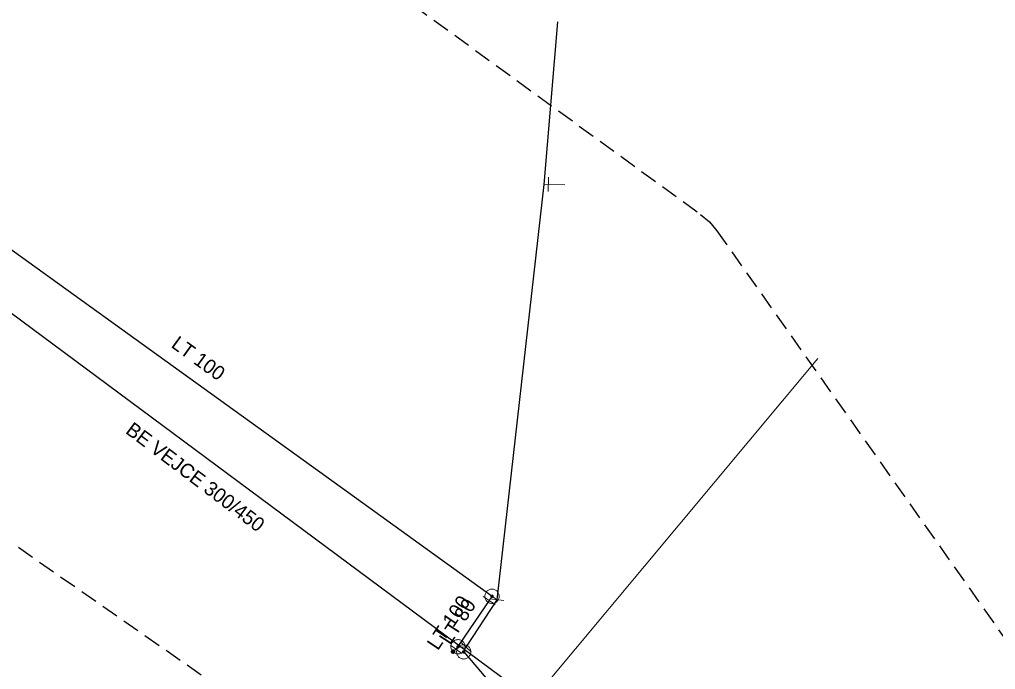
# Model space of a CAD drawing. Extents: x -749365 to -748625, y -965388 to -964881.
# Drawn here: x -748769.4 to -748701, y -965272.1 to -965226.5 of the extents above; entities that cross this region are included whole.
import ezdxf

# ---------------------------------------------------------------- set-up
doc = ezdxf.new("R2010")
doc.units = 0
doc.header["$LTSCALE"] = 0.4
doc.linetypes.add('MEDIUM_DASHED', pattern=[4.5, 3, -1.5])
for name, color, linetype, lineweight in [('1', 7, 'MEDIUM_DASHED', 25), ('11', 7, 'Continuous', 13), ('13', 7, 'Continuous', 13), ('14', 7, 'Continuous', 13), ('17', 7, 'Continuous', 25), ('34', 7, 'Continuous', 13), ('47', 7, 'Continuous', 13), ('9', 7, 'Continuous', 13)]:
    doc.layers.add(name, color=color, linetype=linetype, lineweight=lineweight)

msp = doc.modelspace()

# ---------------------------------------------------------------- linework, layer by layer
at = {"layer": '1'}
for points in [[(-748843.645, -965151.367), (-748721.639, -965240.188), (-748721.021, -965240.72), (-748720.498, -965241.345), (-748643.194, -965350.737)], [(-748672.881, -965383.055), (-748747.771, -965278.626), (-748913.896, -965162.751)]]:
    msp.add_lwpolyline(points, dxfattribs=at)
at = {"layer": '11'}
msp.add_line((-748713.426, -965250.271), (-748733.398, -965274.196), dxfattribs=at)
at = {"layer": '13'}
msp.add_line((-748732.306, -965238.081), (-748731.149, -965238.125), dxfattribs=at)
at = {"layer": '14'}
for p, q in [((-748732.62, -965238.09), (-748732.306, -965238.081)), ((-748736.449, -965267.23), (-748736.25, -965266.93)), ((-748735.92, -965267.17), (-748736.25, -965266.93)), ((-748738.76, -965270.64), (-748738.98, -965270.8)), ((-748738.638, -965270.465), (-748738.76, -965270.64)), ((-748738.638, -965270.465), (-748738.079, -965270.489)), ((-748738.079, -965270.489), (-748738.234, -965270.822))]:
    msp.add_line(p, q, dxfattribs=at)
at = {"layer": '14', "lineweight": 25}
msp.add_lwpolyline([(-748815.416, -965213.761), (-748783.169, -965237.598), (-748775.37, -965243.07), (-748733.398, -965274.196)], dxfattribs=at)
at = {"layer": '17'}
for points in [[(-748844.32, -965190.469), (-748841.57, -965190.28), (-748829.535, -965199.166), (-748824.8, -965202.6), (-748811.05, -965212.52), (-748799.78, -965220.98), (-748785.41, -965231.14), (-748777.69, -965237.149), (-748775.66, -965238.539), (-748746.309, -965259.66), (-748736.25, -965266.93)], [(-748731.663, -965226.705), (-748732.62, -965238.09), (-748735.92, -965267.17), (-748738.079, -965270.489)], [(-748736.449, -965267.23), (-748738.5, -965270.239), (-748738.638, -965270.465)], [(-748738.234, -965270.822), (-748726.585, -965284.577), (-748724.84, -965286.638), (-748719.677, -965293.835), (-748717.51, -965296.688), (-748705.515, -965317.423), (-748697.278, -965331.659), (-748689.392, -965346.28), (-748687.454, -965349.21), (-748674.822, -965372.635), (-748674.485, -965375.898)]]:
    msp.add_lwpolyline(points, dxfattribs=at)
at = {"layer": '34'}
for p, q in [((-748732.287, -965237.581), (-748732.325, -965238.58)), ((-748736.862, -965266.948), (-748736.036, -965267.511)), ((-748735.423, -965267.225), (-748736.416, -965267.113)), ((-748738.356, -965270.935), (-748739.162, -965270.343)), ((-748738.446, -965270.15), (-748737.711, -965270.828))]:
    msp.add_line(p, q, dxfattribs=at)
at = {"layer": '47'}
for points in [[(-748736.655, -965266.637), (-748736.683, -965266.681), (-748736.707, -965266.727), (-748736.725, -965266.776), (-748736.739, -965266.826), (-748736.747, -965266.879), (-748736.749, -965266.931), (-748736.746, -965266.983), (-748736.738, -965267.035), (-748736.724, -965267.085), (-748736.706, -965267.134), (-748736.682, -965267.181), (-748736.653, -965267.224), (-748736.62, -965267.265), (-748736.583, -965267.302), (-748736.542, -965267.335), (-748736.498, -965267.363), (-748736.452, -965267.387), (-748736.402, -965267.405), (-748736.353, -965267.419), (-748736.3, -965267.427), (-748736.248, -965267.429), (-748736.195, -965267.426), (-748736.144, -965267.418), (-748736.093, -965267.405), (-748736.045, -965267.386), (-748735.998, -965267.362), (-748735.954, -965267.333), (-748735.914, -965267.3), (-748735.877, -965267.263), (-748735.844, -965267.222), (-748735.816, -965267.178), (-748735.792, -965267.132), (-748735.773, -965267.083), (-748735.76, -965267.033), (-748735.752, -965266.98), (-748735.749, -965266.928), (-748735.752, -965266.876), (-748735.76, -965266.824), (-748735.774, -965266.773), (-748735.793, -965266.725), (-748735.817, -965266.678), (-748735.845, -965266.634), (-748735.879, -965266.594), (-748735.916, -965266.557), (-748735.957, -965266.524), (-748736.001, -965266.496), (-748736.047, -965266.472), (-748736.096, -965266.453), (-748736.146, -965266.44), (-748736.199, -965266.432), (-748736.251, -965266.429), (-748736.302, -965266.432), (-748736.354, -965266.441), (-748736.405, -965266.455), (-748736.454, -965266.473), (-748736.501, -965266.497), (-748736.544, -965266.526), (-748736.585, -965266.559), (-748736.622, -965266.596)], [(-748736.316, -965266.881), (-748736.321, -965266.889), (-748736.324, -965266.896), (-748736.327, -965266.904), (-748736.33, -965266.912), (-748736.331, -965266.921), (-748736.331, -965266.93), (-748736.331, -965266.938), (-748736.33, -965266.947), (-748736.327, -965266.955), (-748736.324, -965266.963), (-748736.32, -965266.971), (-748736.315, -965266.978), (-748736.31, -965266.984), (-748736.305, -965266.991), (-748736.298, -965266.996), (-748736.29, -965267.001), (-748736.283, -965267.004), (-748736.275, -965267.007), (-748736.267, -965267.01), (-748736.258, -965267.011), (-748736.249, -965267.011), (-748736.241, -965267.011), (-748736.232, -965267.01), (-748736.223, -965267.008), (-748736.216, -965267.004), (-748736.208, -965267), (-748736.201, -965266.995), (-748736.195, -965266.99), (-748736.188, -965266.985), (-748736.183, -965266.978), (-748736.178, -965266.97), (-748736.175, -965266.963), (-748736.172, -965266.955), (-748736.169, -965266.947), (-748736.168, -965266.938), (-748736.167, -965266.93), (-748736.168, -965266.921), (-748736.169, -965266.912), (-748736.171, -965266.903), (-748736.175, -965266.896), (-748736.179, -965266.888), (-748736.184, -965266.881), (-748736.189, -965266.875), (-748736.194, -965266.868), (-748736.201, -965266.863), (-748736.209, -965266.858), (-748736.216, -965266.855), (-748736.224, -965266.852), (-748736.232, -965266.849), (-748736.241, -965266.848), (-748736.249, -965266.847), (-748736.258, -965266.848), (-748736.267, -965266.849), (-748736.275, -965266.852), (-748736.283, -965266.855), (-748736.291, -965266.859), (-748736.298, -965266.864), (-748736.304, -965266.869), (-748736.311, -965266.874)], [(-748738.263, -965270.796), (-748738.231, -965270.755), (-748738.202, -965270.711), (-748738.18, -965270.664), (-748738.161, -965270.615), (-748738.148, -965270.564), (-748738.14, -965270.512), (-748738.138, -965270.46), (-748738.141, -965270.408), (-748738.15, -965270.357), (-748738.163, -965270.306), (-748738.183, -965270.257), (-748738.207, -965270.211), (-748738.235, -965270.167), (-748738.269, -965270.127), (-748738.306, -965270.09), (-748738.347, -965270.058), (-748738.391, -965270.029), (-748738.439, -965270.006), (-748738.487, -965269.988), (-748738.538, -965269.975), (-748738.59, -965269.967), (-748738.642, -965269.965), (-748738.695, -965269.968), (-748738.746, -965269.976), (-748738.796, -965269.99), (-748738.845, -965270.01), (-748738.892, -965270.034), (-748738.935, -965270.062), (-748738.975, -965270.096), (-748739.012, -965270.133), (-748739.044, -965270.174), (-748739.073, -965270.218), (-748739.097, -965270.265), (-748739.114, -965270.314), (-748739.127, -965270.365), (-748739.136, -965270.416), (-748739.138, -965270.469), (-748739.135, -965270.521), (-748739.126, -965270.573), (-748739.112, -965270.623), (-748739.092, -965270.672), (-748739.069, -965270.718), (-748739.04, -965270.762), (-748739.006, -965270.802), (-748738.969, -965270.839), (-748738.928, -965270.871), (-748738.884, -965270.9), (-748738.838, -965270.923), (-748738.788, -965270.941), (-748738.737, -965270.954), (-748738.686, -965270.963), (-748738.634, -965270.964), (-748738.582, -965270.961), (-748738.53, -965270.952), (-748738.479, -965270.939), (-748738.43, -965270.919), (-748738.385, -965270.895), (-748738.34, -965270.867), (-748738.3, -965270.833)], [(-748737.819, -965271.101), (-748737.792, -965271.056), (-748737.77, -965271.008), (-748737.754, -965270.959), (-748737.741, -965270.908), (-748737.735, -965270.856), (-748737.734, -965270.803), (-748737.739, -965270.752), (-748737.749, -965270.7), (-748737.764, -965270.651), (-748737.784, -965270.602), (-748737.81, -965270.556), (-748737.84, -965270.514), (-748737.874, -965270.474), (-748737.913, -965270.438), (-748737.954, -965270.407), (-748737.999, -965270.38), (-748738.047, -965270.358), (-748738.097, -965270.341), (-748738.147, -965270.329), (-748738.199, -965270.323), (-748738.252, -965270.322), (-748738.304, -965270.327), (-748738.355, -965270.337), (-748738.405, -965270.351), (-748738.453, -965270.372), (-748738.499, -965270.398), (-748738.542, -965270.428), (-748738.581, -965270.462), (-748738.617, -965270.501), (-748738.648, -965270.542), (-748738.675, -965270.587), (-748738.697, -965270.635), (-748738.715, -965270.684), (-748738.726, -965270.735), (-748738.732, -965270.787), (-748738.734, -965270.839), (-748738.729, -965270.892), (-748738.719, -965270.943), (-748738.704, -965270.993), (-748738.683, -965271.041), (-748738.657, -965271.087), (-748738.628, -965271.13), (-748738.593, -965271.169), (-748738.554, -965271.205), (-748738.513, -965271.236), (-748738.468, -965271.263), (-748738.42, -965271.285), (-748738.372, -965271.302), (-748738.32, -965271.314), (-748738.268, -965271.32), (-748738.216, -965271.322), (-748738.164, -965271.317), (-748738.113, -965271.307), (-748738.063, -965271.291), (-748738.014, -965271.271), (-748737.968, -965271.245), (-748737.926, -965271.215), (-748737.886, -965271.181), (-748737.85, -965271.142)], [(-748738.576, -965270.519), (-748738.57, -965270.512), (-748738.566, -965270.505), (-748738.563, -965270.497), (-748738.559, -965270.49), (-748738.557, -965270.481), (-748738.556, -965270.472), (-748738.555, -965270.464), (-748738.556, -965270.455), (-748738.558, -965270.447), (-748738.56, -965270.439), (-748738.563, -965270.43), (-748738.567, -965270.423), (-748738.572, -965270.416), (-748738.576, -965270.409), (-748738.583, -965270.403), (-748738.59, -965270.397), (-748738.597, -965270.393), (-748738.605, -965270.39), (-748738.612, -965270.386), (-748738.621, -965270.384), (-748738.63, -965270.383), (-748738.638, -965270.382), (-748738.647, -965270.383), (-748738.656, -965270.384), (-748738.663, -965270.387), (-748738.672, -965270.39), (-748738.679, -965270.394), (-748738.686, -965270.399), (-748738.693, -965270.403), (-748738.699, -965270.41), (-748738.705, -965270.417), (-748738.709, -965270.424), (-748738.712, -965270.432), (-748738.716, -965270.439), (-748738.718, -965270.448), (-748738.719, -965270.456), (-748738.72, -965270.465), (-748738.719, -965270.474), (-748738.718, -965270.483), (-748738.715, -965270.49), (-748738.712, -965270.499), (-748738.708, -965270.506), (-748738.703, -965270.513), (-748738.699, -965270.52), (-748738.692, -965270.526), (-748738.685, -965270.532), (-748738.678, -965270.536), (-748738.67, -965270.539), (-748738.663, -965270.543), (-748738.654, -965270.545), (-748738.646, -965270.546), (-748738.637, -965270.547), (-748738.628, -965270.546), (-748738.62, -965270.544), (-748738.612, -965270.542), (-748738.603, -965270.539), (-748738.596, -965270.535), (-748738.589, -965270.53), (-748738.582, -965270.526)], [(-748738.165, -965270.867), (-748738.16, -965270.86), (-748738.158, -965270.852), (-748738.155, -965270.844), (-748738.153, -965270.836), (-748738.152, -965270.827), (-748738.152, -965270.819), (-748738.152, -965270.81), (-748738.154, -965270.802), (-748738.157, -965270.794), (-748738.16, -965270.786), (-748738.164, -965270.778), (-748738.169, -965270.771), (-748738.175, -965270.765), (-748738.18, -965270.759), (-748738.188, -965270.753), (-748738.195, -965270.748), (-748738.203, -965270.746), (-748738.211, -965270.743), (-748738.219, -965270.741), (-748738.228, -965270.74), (-748738.236, -965270.74), (-748738.245, -965270.74), (-748738.253, -965270.742), (-748738.262, -965270.744), (-748738.269, -965270.748), (-748738.277, -965270.752), (-748738.284, -965270.757), (-748738.29, -965270.763), (-748738.296, -965270.768), (-748738.302, -965270.776), (-748738.307, -965270.783), (-748738.309, -965270.791), (-748738.312, -965270.799), (-748738.314, -965270.807), (-748738.315, -965270.816), (-748738.316, -965270.824), (-748738.315, -965270.833), (-748738.313, -965270.841), (-748738.311, -965270.85), (-748738.307, -965270.857), (-748738.303, -965270.865), (-748738.298, -965270.872), (-748738.292, -965270.878), (-748738.287, -965270.884), (-748738.279, -965270.89), (-748738.272, -965270.895), (-748738.264, -965270.897), (-748738.256, -965270.9), (-748738.248, -965270.902), (-748738.239, -965270.903), (-748738.231, -965270.904), (-748738.222, -965270.903), (-748738.214, -965270.901), (-748738.206, -965270.898), (-748738.198, -965270.895), (-748738.19, -965270.891), (-748738.183, -965270.886), (-748738.177, -965270.88), (-748738.171, -965270.875)]]:
    msp.add_lwpolyline(points, close=True, dxfattribs=at)
at = {"layer": '9'}
for points in [[(-748739.106, -965270.8), (-748739.106, -965270.813), (-748739.103, -965270.826), (-748739.101, -965270.839), (-748739.096, -965270.851), (-748739.09, -965270.863), (-748739.083, -965270.874), (-748739.075, -965270.884), (-748739.065, -965270.894), (-748739.054, -965270.902), (-748739.044, -965270.909), (-748739.032, -965270.915), (-748739.02, -965270.92), (-748739.007, -965270.923), (-748738.994, -965270.925), (-748738.981, -965270.927), (-748738.968, -965270.926), (-748738.955, -965270.924), (-748738.942, -965270.921), (-748738.929, -965270.916), (-748738.918, -965270.91), (-748738.907, -965270.903), (-748738.897, -965270.895), (-748738.887, -965270.885), (-748738.879, -965270.875), (-748738.872, -965270.864), (-748738.866, -965270.852), (-748738.861, -965270.84), (-748738.858, -965270.827), (-748738.856, -965270.814), (-748738.853, -965270.801), (-748738.855, -965270.788), (-748738.857, -965270.775), (-748738.86, -965270.762), (-748738.865, -965270.75), (-748738.87, -965270.738), (-748738.878, -965270.727), (-748738.886, -965270.717), (-748738.896, -965270.707), (-748738.906, -965270.699), (-748738.917, -965270.692), (-748738.929, -965270.686), (-748738.941, -965270.681), (-748738.954, -965270.678), (-748738.967, -965270.676), (-748738.98, -965270.675), (-748738.993, -965270.675), (-748739.005, -965270.677), (-748739.019, -965270.68), (-748739.031, -965270.685), (-748739.043, -965270.691), (-748739.054, -965270.698), (-748739.064, -965270.706), (-748739.074, -965270.716), (-748739.081, -965270.726), (-748739.089, -965270.737), (-748739.095, -965270.749), (-748739.1, -965270.761), (-748739.103, -965270.774), (-748739.105, -965270.787)], [(-748739.086, -965270.8), (-748739.087, -965270.811), (-748739.085, -965270.822), (-748739.081, -965270.833), (-748739.078, -965270.843), (-748739.073, -965270.853), (-748739.067, -965270.862), (-748739.059, -965270.871), (-748739.052, -965270.879), (-748739.043, -965270.886), (-748739.034, -965270.892), (-748739.024, -965270.897), (-748739.014, -965270.901), (-748739.003, -965270.904), (-748738.992, -965270.907), (-748738.981, -965270.907), (-748738.97, -965270.907), (-748738.959, -965270.905), (-748738.948, -965270.902), (-748738.938, -965270.898), (-748738.928, -965270.893), (-748738.919, -965270.887), (-748738.91, -965270.88), (-748738.902, -965270.872), (-748738.895, -965270.863), (-748738.889, -965270.854), (-748738.884, -965270.844), (-748738.88, -965270.834), (-748738.877, -965270.823), (-748738.875, -965270.812), (-748738.874, -965270.801), (-748738.874, -965270.79), (-748738.875, -965270.779), (-748738.879, -965270.768), (-748738.883, -965270.758), (-748738.888, -965270.748), (-748738.894, -965270.739), (-748738.901, -965270.73), (-748738.909, -965270.722), (-748738.918, -965270.715), (-748738.927, -965270.709), (-748738.937, -965270.704), (-748738.946, -965270.7), (-748738.958, -965270.697), (-748738.968, -965270.695), (-748738.98, -965270.695), (-748738.991, -965270.694), (-748739.002, -965270.696), (-748739.013, -965270.699), (-748739.022, -965270.703), (-748739.032, -965270.708), (-748739.042, -965270.714), (-748739.051, -965270.721), (-748739.059, -965270.729), (-748739.066, -965270.738), (-748739.071, -965270.747), (-748739.076, -965270.757), (-748739.081, -965270.767), (-748739.084, -965270.778), (-748739.086, -965270.789)], [(-748739.067, -965270.8), (-748739.067, -965270.809), (-748739.066, -965270.818), (-748739.063, -965270.827), (-748739.059, -965270.835), (-748739.056, -965270.843), (-748739.051, -965270.851), (-748739.044, -965270.858), (-748739.039, -965270.864), (-748739.032, -965270.87), (-748739.024, -965270.875), (-748739.016, -965270.879), (-748739.008, -965270.882), (-748738.999, -965270.885), (-748738.99, -965270.886), (-748738.981, -965270.888), (-748738.972, -965270.887), (-748738.963, -965270.886), (-748738.954, -965270.883), (-748738.946, -965270.88), (-748738.938, -965270.876), (-748738.929, -965270.871), (-748738.923, -965270.865), (-748738.917, -965270.859), (-748738.911, -965270.852), (-748738.906, -965270.844), (-748738.902, -965270.836), (-748738.899, -965270.828), (-748738.896, -965270.819), (-748738.895, -965270.81), (-748738.892, -965270.801), (-748738.894, -965270.792), (-748738.895, -965270.783), (-748738.897, -965270.774), (-748738.901, -965270.766), (-748738.905, -965270.758), (-748738.91, -965270.75), (-748738.916, -965270.743), (-748738.922, -965270.737), (-748738.929, -965270.731), (-748738.937, -965270.726), (-748738.945, -965270.722), (-748738.953, -965270.719), (-748738.962, -965270.716), (-748738.971, -965270.715), (-748738.98, -965270.714), (-748738.989, -965270.714), (-748738.998, -965270.715), (-748739.007, -965270.718), (-748739.015, -965270.721), (-748739.022, -965270.725), (-748739.031, -965270.73), (-748739.038, -965270.736), (-748739.044, -965270.742), (-748739.049, -965270.749), (-748739.054, -965270.757), (-748739.059, -965270.765), (-748739.062, -965270.773), (-748739.065, -965270.782), (-748739.066, -965270.791)], [(-748739.047, -965270.8), (-748739.047, -965270.807), (-748739.046, -965270.814), (-748739.044, -965270.821), (-748739.042, -965270.827), (-748739.039, -965270.833), (-748739.035, -965270.839), (-748739.031, -965270.845), (-748739.026, -965270.85), (-748739.02, -965270.854), (-748739.014, -965270.858), (-748739.008, -965270.861), (-748739.002, -965270.864), (-748738.995, -965270.865), (-748738.988, -965270.868), (-748738.981, -965270.868), (-748738.973, -965270.868), (-748738.967, -965270.866), (-748738.96, -965270.865), (-748738.954, -965270.862), (-748738.946, -965270.859), (-748738.942, -965270.855), (-748738.936, -965270.851), (-748738.931, -965270.846), (-748738.927, -965270.84), (-748738.923, -965270.834), (-748738.919, -965270.828), (-748738.917, -965270.822), (-748738.915, -965270.815), (-748738.914, -965270.808), (-748738.913, -965270.801), (-748738.913, -965270.794), (-748738.914, -965270.787), (-748738.916, -965270.78), (-748738.919, -965270.774), (-748738.922, -965270.767), (-748738.926, -965270.762), (-748738.929, -965270.756), (-748738.934, -965270.751), (-748738.941, -965270.747), (-748738.946, -965270.743), (-748738.953, -965270.74), (-748738.959, -965270.737), (-748738.966, -965270.735), (-748738.973, -965270.734), (-748738.98, -965270.734), (-748738.987, -965270.734), (-748738.994, -965270.734), (-748739, -965270.736), (-748739.007, -965270.739), (-748739.013, -965270.742), (-748739.019, -965270.746), (-748739.025, -965270.75), (-748739.03, -965270.755), (-748739.034, -965270.761), (-748739.038, -965270.766), (-748739.041, -965270.773), (-748739.044, -965270.779), (-748739.044, -965270.786), (-748739.047, -965270.793)], [(-748739.027, -965270.8), (-748739.027, -965270.805), (-748739.027, -965270.81), (-748739.026, -965270.815), (-748739.024, -965270.819), (-748739.022, -965270.824), (-748739.019, -965270.828), (-748739.016, -965270.831), (-748739.012, -965270.835), (-748739.009, -965270.838), (-748739.005, -965270.841), (-748739, -965270.843), (-748738.995, -965270.845), (-748738.991, -965270.846), (-748738.986, -965270.848), (-748738.981, -965270.848), (-748738.976, -965270.848), (-748738.971, -965270.847), (-748738.966, -965270.846), (-748738.962, -965270.844), (-748738.956, -965270.842), (-748738.953, -965270.839), (-748738.949, -965270.836), (-748738.946, -965270.832), (-748738.943, -965270.829), (-748738.94, -965270.825), (-748738.938, -965270.82), (-748738.936, -965270.816), (-748738.934, -965270.811), (-748738.934, -965270.806), (-748738.933, -965270.801), (-748738.933, -965270.796), (-748738.934, -965270.791), (-748738.934, -965270.786), (-748738.937, -965270.782), (-748738.939, -965270.777), (-748738.942, -965270.773), (-748738.945, -965270.769), (-748738.948, -965270.766), (-748738.951, -965270.763), (-748738.956, -965270.76), (-748738.961, -965270.758), (-748738.965, -965270.756), (-748738.97, -965270.755), (-748738.975, -965270.754), (-748738.98, -965270.754), (-748738.985, -965270.754), (-748738.99, -965270.755), (-748738.995, -965270.755), (-748738.999, -965270.757), (-748739.004, -965270.759), (-748739.008, -965270.762), (-748739.011, -965270.765), (-748739.015, -965270.768), (-748739.017, -965270.772), (-748739.021, -965270.776), (-748739.022, -965270.781), (-748739.025, -965270.785), (-748739.026, -965270.79), (-748739.027, -965270.795)], [(-748739.007, -965270.8), (-748739.007, -965270.803), (-748739.008, -965270.806), (-748739.007, -965270.808), (-748739.005, -965270.811), (-748739.005, -965270.814), (-748739.003, -965270.816), (-748739, -965270.818), (-748738.999, -965270.82), (-748738.997, -965270.822), (-748738.995, -965270.824), (-748738.992, -965270.826), (-748738.989, -965270.827), (-748738.987, -965270.827), (-748738.983, -965270.828), (-748738.981, -965270.828), (-748738.978, -965270.828), (-748738.975, -965270.828), (-748738.972, -965270.827), (-748738.97, -965270.826), (-748738.967, -965270.825), (-748738.965, -965270.823), (-748738.962, -965270.821), (-748738.96, -965270.819), (-748738.959, -965270.817), (-748738.956, -965270.815), (-748738.956, -965270.812), (-748738.954, -965270.809), (-748738.954, -965270.807), (-748738.953, -965270.804), (-748738.951, -965270.801), (-748738.953, -965270.798), (-748738.953, -965270.795), (-748738.954, -965270.792), (-748738.955, -965270.79), (-748738.956, -965270.787), (-748738.958, -965270.785), (-748738.959, -965270.782), (-748738.961, -965270.78), (-748738.964, -965270.779), (-748738.966, -965270.777), (-748738.968, -965270.776), (-748738.971, -965270.775), (-748738.973, -965270.774), (-748738.977, -965270.774), (-748738.98, -965270.773), (-748738.983, -965270.774), (-748738.986, -965270.773), (-748738.988, -965270.775), (-748738.991, -965270.775), (-748738.994, -965270.776), (-748738.995, -965270.778), (-748738.998, -965270.779), (-748739, -965270.781), (-748739.002, -965270.784), (-748739.004, -965270.786), (-748739.005, -965270.789), (-748739.005, -965270.791), (-748739.007, -965270.794), (-748739.007, -965270.797)], [(-748738.988, -965270.8), (-748738.988, -965270.802), (-748738.988, -965270.802), (-748738.987, -965270.802), (-748738.987, -965270.804), (-748738.988, -965270.805), (-748738.986, -965270.805), (-748738.986, -965270.805), (-748738.986, -965270.807), (-748738.986, -965270.807), (-748738.985, -965270.808), (-748738.983, -965270.808), (-748738.983, -965270.808), (-748738.983, -965270.809), (-748738.981, -965270.809), (-748738.981, -965270.809), (-748738.98, -965270.809), (-748738.978, -965270.809), (-748738.978, -965270.808), (-748738.978, -965270.808), (-748738.976, -965270.808), (-748738.976, -965270.807), (-748738.976, -965270.807), (-748738.975, -965270.806), (-748738.975, -965270.806), (-748738.973, -965270.805), (-748738.973, -965270.804), (-748738.972, -965270.803), (-748738.972, -965270.803), (-748738.972, -965270.802), (-748738.972, -965270.801), (-748738.972, -965270.8), (-748738.972, -965270.799), (-748738.972, -965270.799), (-748738.973, -965270.798), (-748738.973, -965270.797), (-748738.973, -965270.796), (-748738.973, -965270.796), (-748738.975, -965270.795), (-748738.975, -965270.795), (-748738.976, -965270.794), (-748738.977, -965270.794), (-748738.978, -965270.793), (-748738.978, -965270.793), (-748738.978, -965270.793), (-748738.98, -965270.793), (-748738.981, -965270.793), (-748738.982, -965270.793), (-748738.982, -965270.793), (-748738.983, -965270.794), (-748738.983, -965270.793), (-748738.985, -965270.795), (-748738.985, -965270.795), (-748738.986, -965270.795), (-748738.986, -965270.795), (-748738.987, -965270.797), (-748738.987, -965270.798), (-748738.987, -965270.799), (-748738.988, -965270.799), (-748738.988, -965270.8)]]:
    msp.add_lwpolyline(points, close=True, dxfattribs=at)

# ---------------------------------------------------------------- texts
at = {"layer": '1'}
for s, rotation, p in [('LT 100', 324, (-748758.797, -965249.443)), ('BE VEJCE 300/450', 323, (-748761.991, -965255.462)), ('LT 100', 56, (-748740.05, -965270.773)), ('LT 80 ', 57, (-748739.189, -965270.388))]:
    msp.add_text(s, height=1, rotation=rotation, dxfattribs=at).set_placement(p)

doc.saveas('drawing.dxf')
